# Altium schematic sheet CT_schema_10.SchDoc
size 387 x 385 mm
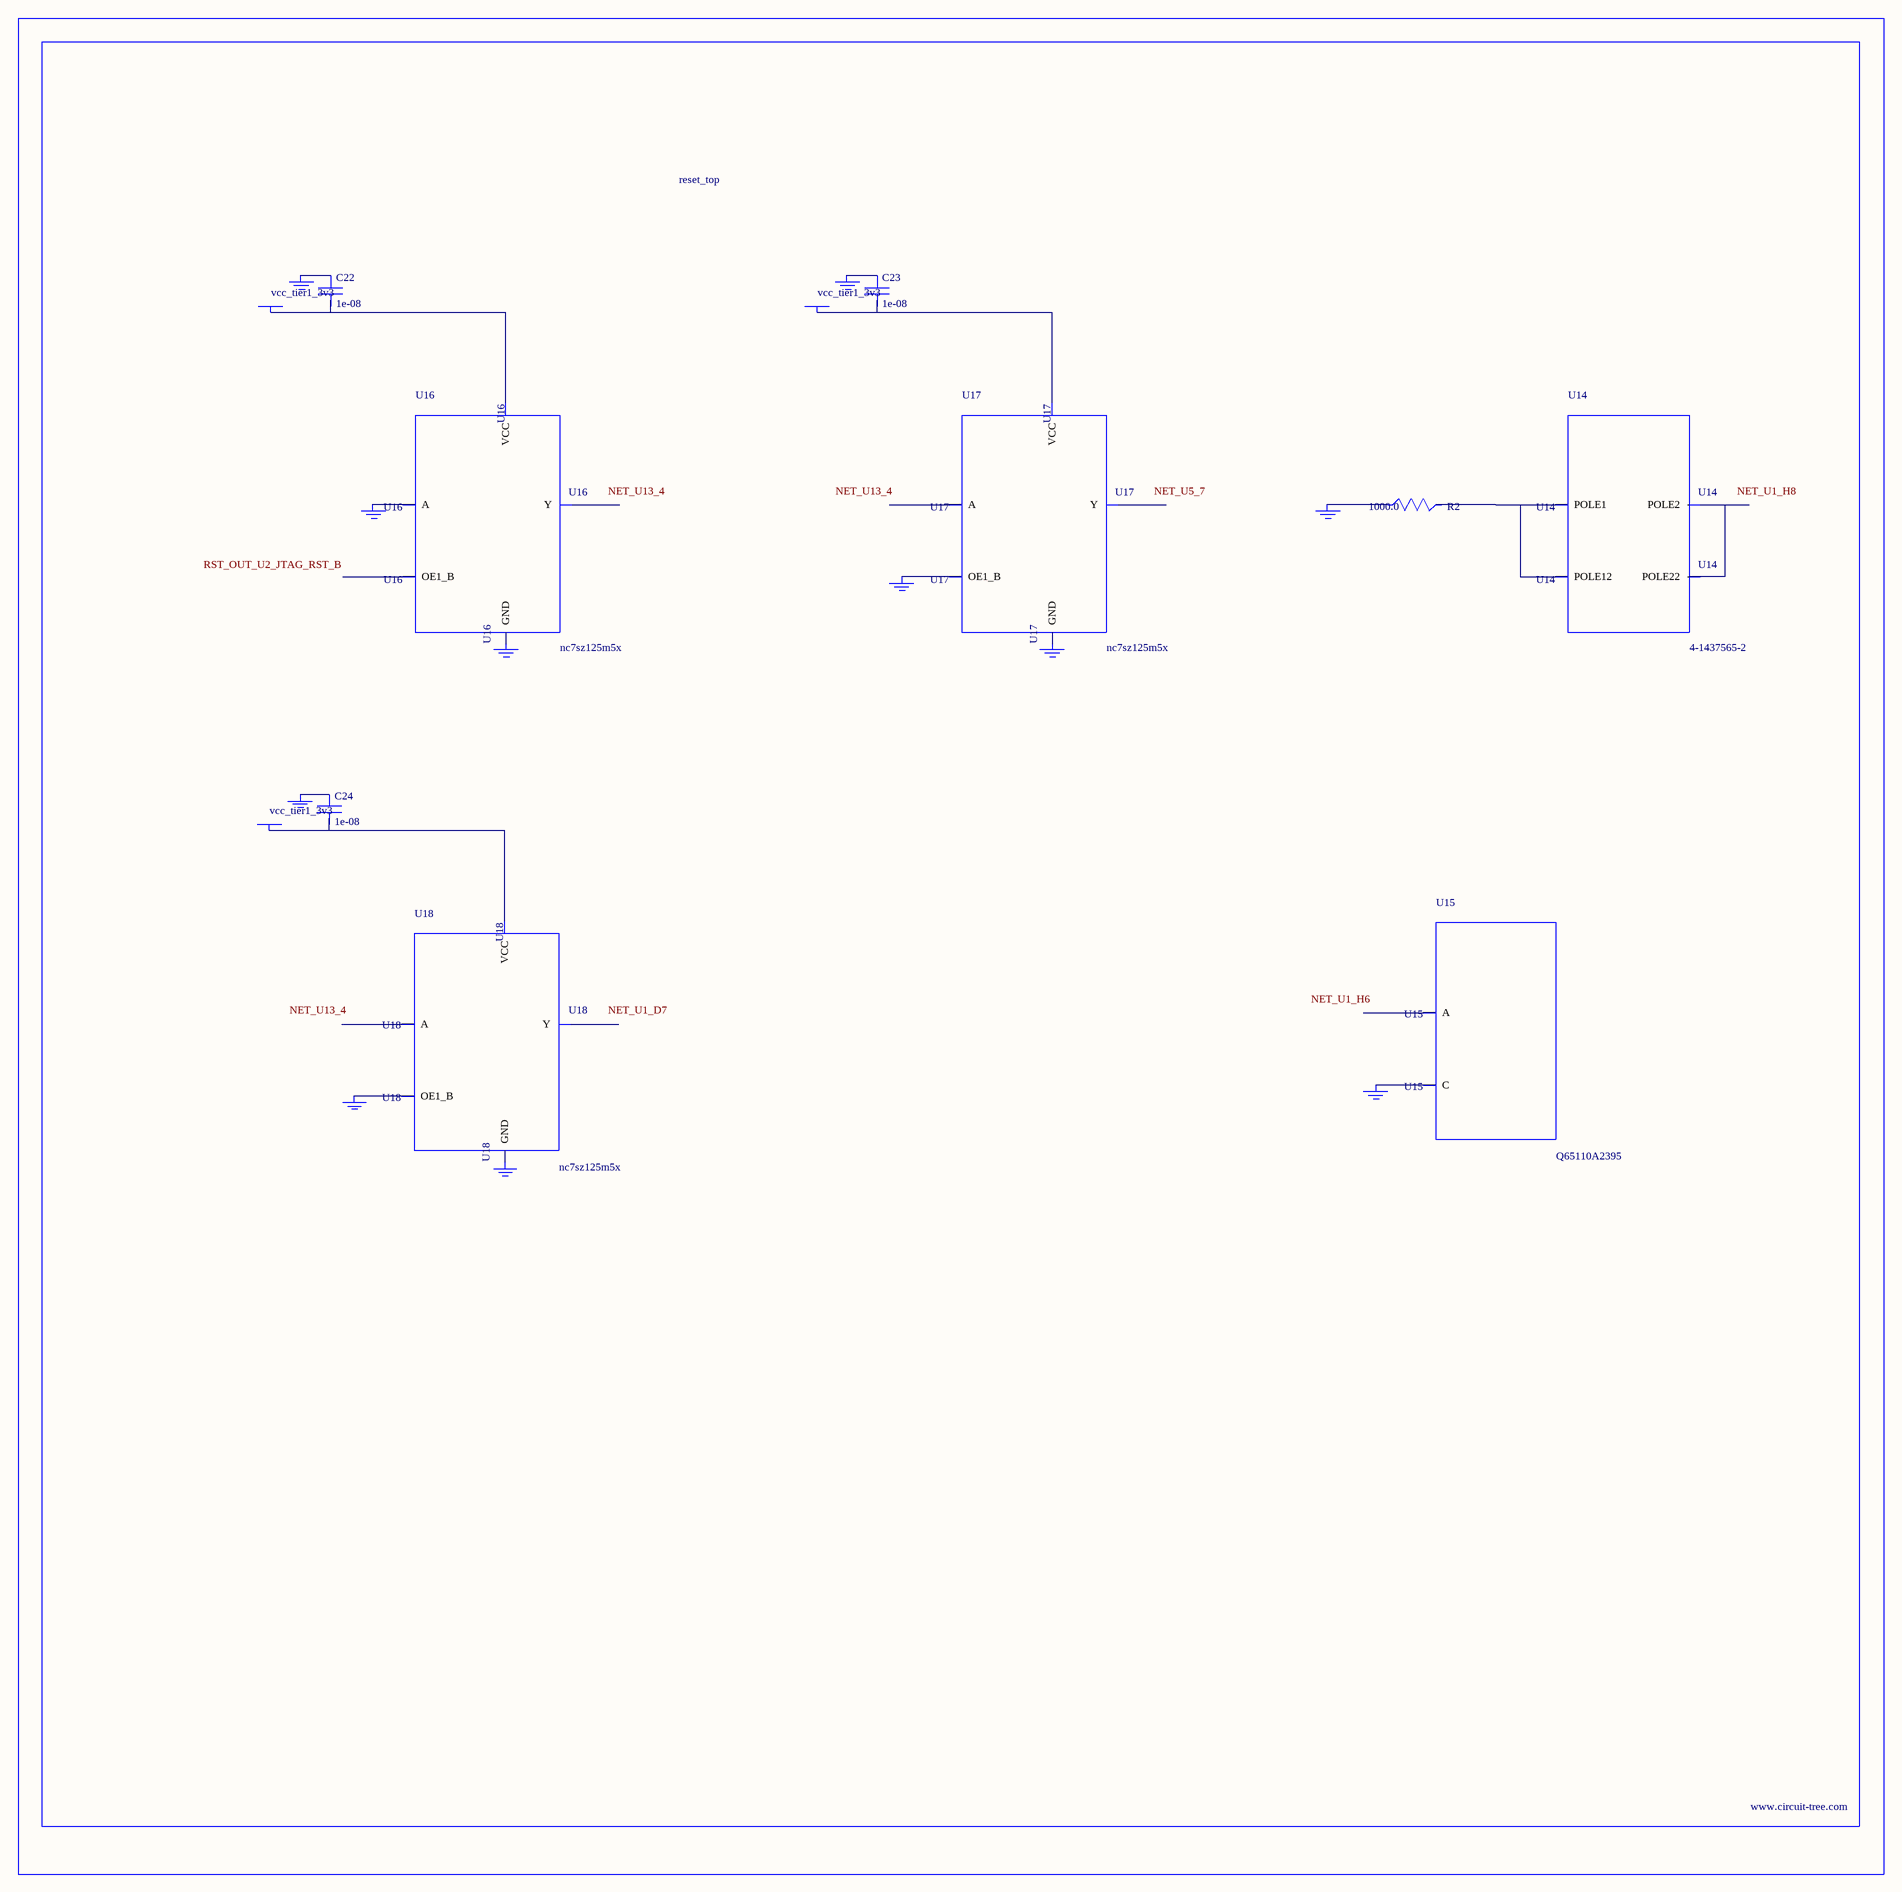
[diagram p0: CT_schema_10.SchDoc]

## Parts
BORDER9  (no value)
C22  1e-08  [C0402]
C23  1e-08  [C0402]
C24  1e-08  [C0402]
GND_INSTANCE_9_0  (no value)
GND_INSTANCE_9_1  (no value)
GND_INSTANCE_9_2  (no value)
GND_INSTANCE_9_3  (no value)
GND_INSTANCE_9_4  (no value)
GND_INSTANCE_9_5  (no value)
GND_INSTANCE_9_6  (no value)
GND_INSTANCE_9_7  (no value)
GND_INSTANCE_9_8  (no value)
GND_INSTANCE_9_9  (no value)
GND_INSTANCE_9_10  (no value)
POWER_INSTANCE_9_0  vcc_tier1_3v3
POWER_INSTANCE_9_1  vcc_tier1_3v3
POWER_INSTANCE_9_2  vcc_tier1_3v3
R2  1000.0  [R0603]
U14  4-1437565-2  [SW_4-1437565-2]
U15  Q65110A2395  [LGM67K-G1J2-24-Z]
U16  nc7sz125m5x  [NC7SZ125M5X]
U17  nc7sz125m5x  [NC7SZ125M5X]
U18  nc7sz125m5x  [NC7SZ125M5X]

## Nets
NetC22_1: C22.1 GND_INSTANCE_9_2.0(GND)
NetC22_2: C22.2 POWER_INSTANCE_9_0.0(PWR) U16.5(VCC)
NetC23_1: C23.1 GND_INSTANCE_9_5.0(GND)
NetC23_2: C23.2 POWER_INSTANCE_9_1.0(PWR) U17.5(VCC)
NetC24_1: C24.1 GND_INSTANCE_9_8.0(GND)
NetC24_2: C24.2 POWER_INSTANCE_9_2.0(PWR) U18.5(VCC)
NetGND_INSTANCE_9_0_0: GND_INSTANCE_9_0.0(GND) R2.1
NetGND_INSTANCE_9_1_0: GND_INSTANCE_9_1.0(GND) U15.C
NetGND_INSTANCE_9_3_0: GND_INSTANCE_9_3.0(GND) U16.2(A)
NetGND_INSTANCE_9_4_0: GND_INSTANCE_9_4.0(GND) U16.3(GND)
NetGND_INSTANCE_9_6_0: GND_INSTANCE_9_6.0(GND) U17.1(OE1_B)
NetGND_INSTANCE_9_7_0: GND_INSTANCE_9_7.0(GND) U17.3(GND)
NetGND_INSTANCE_9_9_0: GND_INSTANCE_9_9.0(GND) U18.1(OE1_B)
NetGND_INSTANCE_9_10_0: GND_INSTANCE_9_10.0(GND) U18.3(GND)
NetR2_2: R2.2 U14.1(POLE1) U14.2(POLE12)
NetU14_3: U14.3(POLE2) U14.4(POLE22)

Not connected (* = marked no-connect by the designer): U15 A; U16 1(OE1_B) 4(Y); U17 2(A) 4(Y); U18 2(A) 4(Y)

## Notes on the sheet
- Labels drawn without touching a wire or pin: NET_U1_D7, NET_U1_H6, NET_U1_H8, NET_U5_7, NET_U13_4, RST_OUT_U2_JTAG_RST_B

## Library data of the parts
BORDER9 = BORDER_PAGE9
C22-C24 = C0402C103K3RAC
GND_INSTANCE_9_0-GND_INSTANCE_9_10 = GND
POWER_INSTANCE_9_0-POWER_INSTANCE_9_2 = PWR
R2 = RC0603JR-071KL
